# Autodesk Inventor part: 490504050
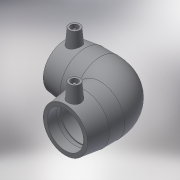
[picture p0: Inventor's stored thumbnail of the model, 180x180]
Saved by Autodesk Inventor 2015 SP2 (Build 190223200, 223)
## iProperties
Created: 2017-06
Part Number: 490504050
Material: Generic
Description: PLASSON 90° ELBOW 50
Document SubType Name: Modeling
Designer: KIM
Mass: 55.0731 g
Surface Area: 148.067 cm^2
Volume: 55.0731 cm^3
Density: 1 g/cm^3
Appearance: Default
Author: KIM
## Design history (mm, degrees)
derived "490504.ipt"
feature "Solid1::490504.ipt"
tag "TaggingFeature1"
body "Solid1"
other parameters: "d2" = 68, "d4" = 27, "d5" = 61.2, "d8" = 168 deg, "d10" = 19.2, "d11" = 6.4, "d14" = 17.6296, "d19" = 3.52592, "d20" = 168 deg, "d22" = 62.56, "d23" = 68, "d24" = 60.6832, "d29" = 52, "d30" = 15, "d31" = 64.8, "d34" = 5 deg, "d35" = 15, "d39" = 5 deg, "d41" = 4, "d42" = 14, "d43" = 0, "d45" = 4, "d46" = 14, "d47" = 0, "d50" = 42.5, "d51" = 19.2, "d52" = 48, "d54" = 90 deg, "d67" = 45 deg, "d71" = 90 deg, "d75" = 3.4, "d82" = 45 deg, "d83" = 48, "d84" = 61.2, "d86" = 30.6, "d87" = 90 deg, "d90" = 48, "d91" = 0, "d92" = 48, "d93" = 0, "d94" = 90 deg, "d95" = 31.28, "d98" = 108, "d101" = 3, "d102" = 0, "d103" = 3, "d104" = 0, "d105" = 13.92, "d106" = 3.48, "d107" = 108, "d110" = 26.4, "L_" = 108, "L_1" = 48, "D_" = 68, "A_" = 52, "d_2" = 12
